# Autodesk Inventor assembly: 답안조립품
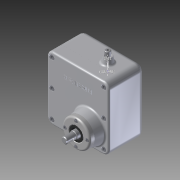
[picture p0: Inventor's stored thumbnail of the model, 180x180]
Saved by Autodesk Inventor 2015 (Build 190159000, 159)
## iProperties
Created: 2015-10
Part Number: 답안조립품
Document SubType Name: Assembly
Designer: PHO-02
Mass: 1079.52 g
Surface Area: 1352.06 cm^2
Volume: 279.093 cm^3
Density: 3.86796 g/cm^3
Author: PHO-02
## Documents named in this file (15)
- C:\Users\PHO-02\Desktop\351007V1010\답안조립품.iam
- C:\Users\PHO-02\Desktop\351007V1010\본체.ipt
- C:\Users\PHO-02\Desktop\351007V1010\베어링 6002.ipt
- C:\Users\PHO-02\Desktop\351007V1010\편심 축.ipt
- C:\Users\PHO-02\Desktop\351007V1010\로드 축.ipt
- C:\Users\PHO-02\Desktop\351007V1010\로드.ipt
- C:\Users\PHO-02\Desktop\351007V1010\슬라이드.ipt
- C:\Users\PHO-02\Desktop\351007V1010\가변 스프링.ipt
- C:\Users\PHO-02\Desktop\351007V1010\커버.ipt
- C:\Users\PHO-02\Desktop\351007V1010\오일실 12 x 22.ipt
- C:\Users\PHO-02\Desktop\351007V1010\오일실 15 x 25.ipt
- C:\Users\PHO-02\Desktop\351007V1010\축 커버.ipt
- C:\Users\PHO-02\Desktop\351007V1010\베어링 6001.ipt
- C:\Users\PHO-02\Desktop\351007V1010\M3 x 0.5.ipt
- C:\Users\PHO-02\Desktop\351007V1010\M4 x 0.7.ipt
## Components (11 placed, 3 different names)
1. 가변 스프링:1
2. M3 x 0.5:1 — 각도:3
3. M3 x 0.5:2
4. M3 x 0.5:3
5. M3 x 0.5:4
6. M4 x 0.7:1 — 각도:4
7. M4 x 0.7:2
8. M4 x 0.7:3
9. M4 x 0.7:4
10. M4 x 0.7:5
11. M4 x 0.7:6
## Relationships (2: Angle 2)
- 각도:3 [Angle]: M3 x 0.5:1
- 각도:4 [Angle]: M4 x 0.7:1
